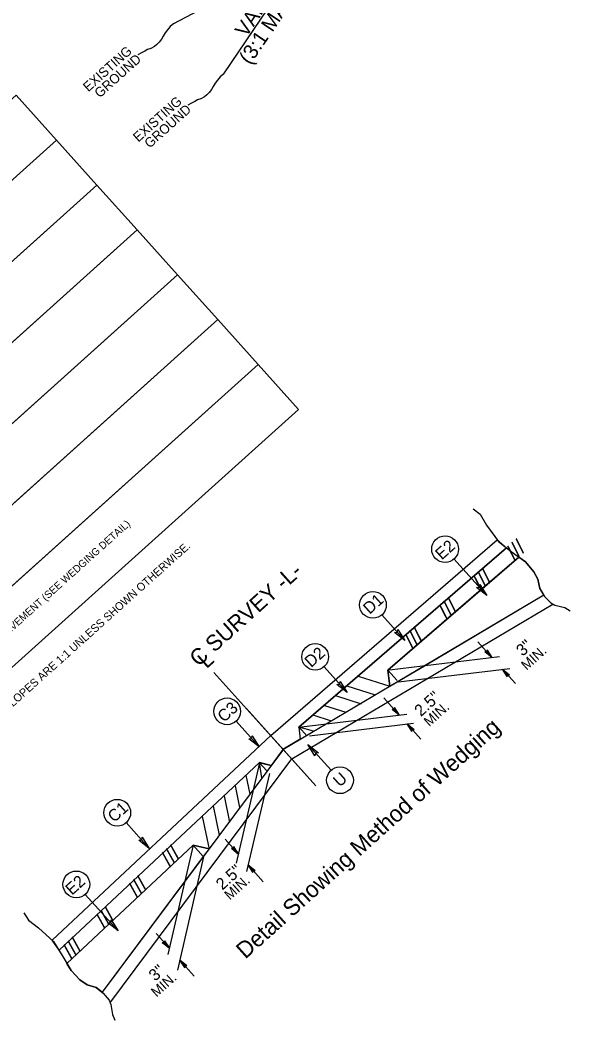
# Model space of a CAD drawing. Extents: x 2488411 to 2488707, y 383669 to 383962.
# Drawn here: x 2488541.5 to 2488578.8, y 383777 to 383844.8 of the extents above; entities that cross this region are included whole.
import ezdxf

# ---------------------------------------------------------------- set-up
doc = ezdxf.new("R2010")
doc.units = 0
for name, color, linetype in [('Old_Level_44', 7, 'Continuous'), ('Prop Dimension', 7, 'Continuous'), ('Prop DSN Text', 7, 'Continuous'), ('Prop Grid Mask', 7, 'Continuous'), ('Prop PFL Pipe Hydraulic Data CELL', 7, 'Continuous'), ('Prop Roadway Profile Bench Mark Info Text', 7, 'Continuous'), ('Sheet Sticker Preliminary CELL', 7, 'Continuous'), ('Sheet Title CELL', 7, 'Continuous'), ('Typical Hinge Slope Arterial CELL', 7, 'Continuous'), ('Typical Text General CELL', 7, 'Continuous'), ('Typical Text ID Circle CELL', 7, 'Continuous')]:
    doc.layers.add(name, color=color, linetype=linetype)

msp = doc.modelspace()

# ---------------------------------------------------------------- linework, layer by layer
at = {"layer": 'Prop DSN Text'}
for p, q in [((2488570.949, 383808.275), (2488573.176, 383805.798)), ((2488566.059, 383804.497), (2488567.625, 383802.755)), ((2488562.138, 383800.973), (2488563.704, 383799.231)), ((2488556.168, 383797.28), (2488557.734, 383795.538)), ((2488562.611, 383793.957), (2488561.045, 383795.699)), ((2488548.719, 383790.408), (2488550.285, 383788.666)), ((2488545.945, 383785.548), (2488548.172, 383783.071))]:
    msp.add_line(p, q, dxfattribs=at)
for centre in [(2488570.343, 383808.949), (2488565.453, 383805.171), (2488561.533, 383801.647), (2488555.563, 383797.954), (2488563.217, 383793.283), (2488548.113, 383791.082), (2488545.339, 383786.222)]:
    msp.add_circle(centre, 0.906, dxfattribs=at)
at = {"layer": 'Prop Grid Mask'}
for points in [[(2488517.29, 383812.671), (2488514.248, 383809.936), (2488511.513, 383812.978), (2488541.261, 383839.72), (2488543.996, 383836.678), (2488517.29, 383812.671), (2488514.555, 383815.713)], [(2488520.025, 383809.629), (2488516.983, 383806.894), (2488514.248, 383809.936), (2488543.996, 383836.678), (2488546.731, 383833.636), (2488520.025, 383809.629), (2488517.29, 383812.671)], [(2488522.76, 383806.586), (2488519.718, 383803.852), (2488516.983, 383806.894), (2488546.731, 383833.636), (2488549.466, 383830.593), (2488522.76, 383806.586), (2488520.025, 383809.629)], [(2488525.495, 383803.544), (2488522.453, 383800.809), (2488519.718, 383803.852), (2488549.465, 383830.593), (2488552.2, 383827.551), (2488525.495, 383803.544), (2488522.76, 383806.586)], [(2488528.23, 383800.502), (2488525.187, 383797.767), (2488522.453, 383800.809), (2488552.2, 383827.551), (2488554.935, 383824.508), (2488528.23, 383800.502), (2488525.495, 383803.544)], [(2488530.965, 383797.46), (2488527.922, 383794.725), (2488525.187, 383797.767), (2488554.935, 383824.508), (2488557.67, 383821.466), (2488530.965, 383797.46), (2488528.23, 383800.502)], [(2488533.699, 383794.417), (2488530.657, 383791.682), (2488527.922, 383794.725), (2488557.67, 383821.466), (2488560.404, 383818.424), (2488533.699, 383794.417), (2488530.965, 383797.46)]]:
    msp.add_lwpolyline(points, dxfattribs=at)
at = {"layer": 'Prop PFL Pipe Hydraulic Data CELL'}
for p, q in [((2488558.525, 383796.306), (2488573.887, 383809.571)), ((2488558.527, 383796.307), (2488573.887, 383809.571)), ((2488573.887, 383809.571), (2488574.519, 383809.042)), ((2488560.428, 383796.875), (2488574.519, 383809.042)), ((2488574.519, 383809.042), (2488560.428, 383796.875)), ((2488566.469, 383800.747), (2488575.349, 383808.414)), ((2488575.349, 383808.414), (2488572.802, 383806.214)), ((2488559.337, 383795.358), (2488577.035, 383805.842)), ((2488572.802, 383806.214), (2488566.469, 383800.747)), ((2488568.945, 383801.049), (2488577.035, 383805.842)), ((2488559.946, 383794.738), (2488577.657, 383805.229)), ((2488572.573, 383802.655), (2488573.515, 383801.607)), ((2488566.584, 383800.761), (2488574.027, 383801.669)), ((2488573.168, 383801.993), (2488573.039, 383801.98)), ((2488573.515, 383801.607), (2488573.039, 383801.98)), ((2488573.515, 383801.607), (2488573.057, 383801.981)), ((2488573.075, 383801.984), (2488573.515, 383801.607)), ((2488573.515, 383801.607), (2488573.093, 383801.986)), ((2488573.112, 383801.987), (2488573.515, 383801.607)), ((2488573.515, 383801.607), (2488573.131, 383801.989)), ((2488573.15, 383801.99), (2488573.515, 383801.607)), ((2488573.195, 383802.12), (2488573.168, 383801.993)), ((2488573.168, 383801.993), (2488573.515, 383801.607)), ((2488573.515, 383801.607), (2488573.172, 383802.011)), ((2488573.176, 383802.029), (2488573.515, 383801.607)), ((2488573.515, 383801.607), (2488573.18, 383802.047)), ((2488573.183, 383802.066), (2488573.515, 383801.607)), ((2488573.515, 383801.607), (2488573.187, 383802.084)), ((2488573.191, 383802.101), (2488573.515, 383801.607)), ((2488573.515, 383801.607), (2488573.195, 383802.12)), ((2488566.593, 383799.656), (2488568.945, 383801.049)), ((2488561.579, 383792.909), (2488554.667, 383800.598)), ((2488564.447, 383800.345), (2488566.593, 383799.656)), ((2488566.594, 383799.657), (2488566.469, 383800.747)), ((2488566.469, 383800.747), (2488567.105, 383800.04)), ((2488566.469, 383800.747), (2488566.593, 383799.656)), ((2488567.188, 383799.948), (2488574.734, 383800.867)), ((2488574.235, 383800.807), (2488575.11, 383799.833)), ((2488574.235, 383800.807), (2488574.712, 383800.433)), ((2488574.235, 383800.807), (2488574.555, 383800.293)), ((2488574.559, 383800.311), (2488574.235, 383800.807)), ((2488574.235, 383800.807), (2488574.563, 383800.329)), ((2488574.566, 383800.347), (2488574.235, 383800.807)), ((2488574.235, 383800.807), (2488574.57, 383800.366)), ((2488574.573, 383800.384), (2488574.235, 383800.807)), ((2488574.235, 383800.807), (2488574.577, 383800.402)), ((2488574.581, 383800.421), (2488574.235, 383800.807)), ((2488574.6, 383800.422), (2488574.235, 383800.807)), ((2488574.235, 383800.807), (2488574.618, 383800.424)), ((2488574.637, 383800.426), (2488574.235, 383800.807)), ((2488574.235, 383800.807), (2488574.655, 383800.428)), ((2488574.674, 383800.429), (2488574.235, 383800.807)), ((2488574.235, 383800.807), (2488574.693, 383800.431)), ((2488574.555, 383800.293), (2488574.581, 383800.421)), ((2488574.581, 383800.421), (2488574.712, 383800.433)), ((2488563.679, 383799.682), (2488565.61, 383799.062)), ((2488562.92, 383799.027), (2488564.652, 383798.472)), ((2488562.171, 383798.35), (2488563.605, 383797.89)), ((2488566.189, 383798.865), (2488567.232, 383797.705)), ((2488561.579, 383792.909), (2488556.859, 383798.161)), ((2488560.615, 383796.898), (2488567.754, 383797.768)), ((2488561.378, 383797.708), (2488562.63, 383797.307)), ((2488566.884, 383798.091), (2488566.754, 383798.079)), ((2488567.232, 383797.705), (2488566.754, 383798.079)), ((2488567.232, 383797.705), (2488566.773, 383798.08)), ((2488566.791, 383798.082), (2488567.232, 383797.705)), ((2488567.232, 383797.705), (2488566.81, 383798.084)), ((2488566.829, 383798.085), (2488567.232, 383797.705)), ((2488567.232, 383797.705), (2488566.847, 383798.088)), ((2488566.865, 383798.089), (2488567.232, 383797.705)), ((2488566.911, 383798.219), (2488566.884, 383798.091)), ((2488566.884, 383798.091), (2488567.232, 383797.705)), ((2488567.232, 383797.705), (2488566.888, 383798.11)), ((2488566.892, 383798.128), (2488567.232, 383797.705)), ((2488567.232, 383797.705), (2488566.896, 383798.146)), ((2488566.899, 383798.164), (2488567.232, 383797.705)), ((2488567.232, 383797.705), (2488566.903, 383798.182)), ((2488566.907, 383798.201), (2488567.232, 383797.705)), ((2488567.232, 383797.705), (2488566.911, 383798.219)), ((2488561.145, 383796.297), (2488568.213, 383797.159)), ((2488567.771, 383797.105), (2488568.704, 383796.068)), ((2488567.771, 383797.105), (2488568.248, 383796.731)), ((2488567.771, 383797.105), (2488568.092, 383796.591)), ((2488568.095, 383796.61), (2488567.771, 383797.105)), ((2488567.771, 383797.105), (2488568.099, 383796.627)), ((2488568.102, 383796.646), (2488567.771, 383797.105)), ((2488567.771, 383797.105), (2488568.106, 383796.664)), ((2488568.11, 383796.682), (2488567.771, 383797.105)), ((2488567.771, 383797.105), (2488568.114, 383796.7)), ((2488568.118, 383796.719), (2488567.771, 383797.105)), ((2488568.137, 383796.721), (2488567.771, 383797.105)), ((2488567.771, 383797.105), (2488568.155, 383796.722)), ((2488568.173, 383796.724), (2488567.771, 383797.105)), ((2488567.771, 383797.105), (2488568.192, 383796.727)), ((2488568.211, 383796.728), (2488567.771, 383797.105)), ((2488567.771, 383797.105), (2488568.229, 383796.73)), ((2488558.525, 383796.306), (2488543.706, 383782.439)), ((2488543.706, 383782.439), (2488558.525, 383796.306)), ((2488560.415, 383796.844), (2488560.438, 383796.862)), ((2488560.428, 383796.875), (2488560.524, 383796.063)), ((2488560.428, 383796.875), (2488560.524, 383796.063)), ((2488561.426, 383796.606), (2488560.441, 383796.878)), ((2488560.441, 383796.878), (2488560.962, 383796.298)), ((2488568.092, 383796.591), (2488568.118, 383796.719)), ((2488568.118, 383796.719), (2488568.248, 383796.731)), ((2488560.524, 383796.063), (2488559.337, 383795.358)), ((2488559.382, 383795.398), (2488547.079, 383778.914)), ((2488559.337, 383795.358), (2488558.554, 383794.292)), ((2488557.769, 383794.485), (2488544.165, 383781.755)), ((2488557.769, 383794.485), (2488544.165, 383781.755)), ((2488559.934, 383794.727), (2488547.65, 383778.268)), ((2488557.761, 383794.458), (2488556.187, 383787.658)), ((2488557.92, 383793.454), (2488557.754, 383794.462)), ((2488557.754, 383794.462), (2488558.227, 383793.936)), ((2488558.554, 383794.292), (2488557.769, 383794.485)), ((2488557.783, 383794.469), (2488558.554, 383794.292)), ((2488556.829, 383793.618), (2488557.095, 383792.332)), ((2488558.426, 383793.739), (2488556.884, 383787.086)), ((2488556.106, 383792.898), (2488556.411, 383791.424)), ((2488555.354, 383792.225), (2488555.722, 383790.444)), ((2488554.621, 383791.54), (2488555.034, 383789.555)), ((2488553.882, 383790.848), (2488554.346, 383788.607)), ((2488553.266, 383788.878), (2488544.701, 383780.863)), ((2488544.701, 383780.863), (2488553.266, 383788.878)), ((2488553.266, 383788.878), (2488551.55, 383781.472)), ((2488554.34, 383788.638), (2488553.266, 383788.878)), ((2488553.266, 383788.878), (2488553.95, 383788.117)), ((2488553.266, 383788.878), (2488554.337, 383788.639)), ((2488555.42, 383789.289), (2488556.33, 383788.278)), ((2488556.01, 383788.792), (2488555.983, 383788.664)), ((2488556.33, 383788.278), (2488556.001, 383788.755)), ((2488556.006, 383788.774), (2488556.33, 383788.278)), ((2488556.33, 383788.278), (2488556.01, 383788.792)), ((2488553.968, 383788.09), (2488552.209, 383780.417)), ((2488553.949, 383788.118), (2488552.704, 383786.449)), ((2488554.337, 383788.639), (2488553.949, 383788.118)), ((2488555.983, 383788.664), (2488555.853, 383788.651)), ((2488556.33, 383788.278), (2488555.853, 383788.651)), ((2488556.33, 383788.278), (2488555.871, 383788.653)), ((2488555.89, 383788.654), (2488556.33, 383788.278)), ((2488556.33, 383788.278), (2488555.908, 383788.657)), ((2488555.927, 383788.659), (2488556.33, 383788.278)), ((2488556.33, 383788.278), (2488555.946, 383788.66)), ((2488555.964, 383788.662), (2488556.33, 383788.278)), ((2488555.983, 383788.664), (2488556.33, 383788.278)), ((2488556.33, 383788.278), (2488555.987, 383788.682)), ((2488555.99, 383788.7), (2488556.33, 383788.278)), ((2488556.33, 383788.278), (2488555.994, 383788.719)), ((2488555.997, 383788.737), (2488556.33, 383788.278)), ((2488556.99, 383787.544), (2488558.014, 383786.405)), ((2488556.99, 383787.544), (2488557.468, 383787.171)), ((2488556.99, 383787.544), (2488557.311, 383787.029)), ((2488557.314, 383787.048), (2488556.99, 383787.544)), ((2488556.99, 383787.544), (2488557.318, 383787.066)), ((2488557.321, 383787.085), (2488556.99, 383787.544)), ((2488556.99, 383787.544), (2488557.326, 383787.103)), ((2488557.33, 383787.121), (2488556.99, 383787.544)), ((2488556.99, 383787.544), (2488557.333, 383787.139)), ((2488557.337, 383787.157), (2488556.99, 383787.544)), ((2488557.355, 383787.159), (2488556.99, 383787.544)), ((2488556.99, 383787.544), (2488557.374, 383787.161)), ((2488557.392, 383787.163), (2488556.99, 383787.544)), ((2488556.99, 383787.544), (2488557.41, 383787.165)), ((2488557.429, 383787.166), (2488556.99, 383787.544)), ((2488556.99, 383787.544), (2488557.449, 383787.169)), ((2488557.311, 383787.029), (2488557.337, 383787.157)), ((2488557.337, 383787.157), (2488557.468, 383787.171)), ((2488552.704, 383786.449), (2488547.079, 383778.914)), ((2488550.741, 383782.897), (2488551.647, 383781.888)), ((2488544.165, 383781.755), (2488543.706, 383782.439)), ((2488551.3, 383782.275), (2488551.17, 383782.261)), ((2488551.647, 383781.888), (2488551.17, 383782.261)), ((2488551.647, 383781.888), (2488551.188, 383782.264)), ((2488551.208, 383782.266), (2488551.647, 383781.888)), ((2488551.647, 383781.888), (2488551.226, 383782.268)), ((2488551.244, 383782.27), (2488551.647, 383781.888)), ((2488551.647, 383781.888), (2488551.263, 383782.272)), ((2488551.281, 383782.273), (2488551.647, 383781.888)), ((2488551.327, 383782.403), (2488551.3, 383782.275)), ((2488551.3, 383782.275), (2488551.647, 383781.888)), ((2488551.647, 383781.888), (2488551.303, 383782.293)), ((2488551.308, 383782.312), (2488551.647, 383781.888)), ((2488551.647, 383781.888), (2488551.311, 383782.33)), ((2488551.315, 383782.348), (2488551.647, 383781.888)), ((2488551.647, 383781.888), (2488551.319, 383782.366)), ((2488551.323, 383782.385), (2488551.647, 383781.888)), ((2488551.647, 383781.888), (2488551.327, 383782.403)), ((2488552.365, 383781.091), (2488553.334, 383780.012)), ((2488552.365, 383781.091), (2488552.842, 383780.717)), ((2488552.365, 383781.091), (2488552.685, 383780.576)), ((2488552.69, 383780.595), (2488552.365, 383781.091)), ((2488552.365, 383781.091), (2488552.693, 383780.614)), ((2488552.697, 383780.632), (2488552.365, 383781.091)), ((2488552.365, 383781.091), (2488552.7, 383780.65)), ((2488552.704, 383780.668), (2488552.365, 383781.091)), ((2488552.365, 383781.091), (2488552.709, 383780.686)), ((2488552.712, 383780.705), (2488552.365, 383781.091)), ((2488552.731, 383780.706), (2488552.365, 383781.091)), ((2488552.365, 383781.091), (2488552.749, 383780.708)), ((2488552.767, 383780.711), (2488552.365, 383781.091)), ((2488552.365, 383781.091), (2488552.786, 383780.712)), ((2488552.805, 383780.714), (2488552.365, 383781.091)), ((2488552.365, 383781.091), (2488552.823, 383780.716)), ((2488552.685, 383780.576), (2488552.712, 383780.705)), ((2488552.712, 383780.705), (2488552.842, 383780.717))]:
    msp.add_line(p, q, dxfattribs=at)
for points in [[(2488572.237, 383811.688), (2488572.715, 383811.318), (2488573.159, 383810.581), (2488573.967, 383809.468), (2488574.836, 383808.796), (2488575.792, 383808.083), (2488576.369, 383807.415), (2488576.634, 383806.904), (2488576.767, 383806.272), (2488577.096, 383805.745), (2488577.517, 383805.302), (2488577.791, 383805.159), (2488578.457, 383804.983), (2488578.815, 383804.773)], [(2488577.035, 383805.842), (2488576.767, 383806.272), (2488576.634, 383806.904), (2488576.369, 383807.415), (2488575.792, 383808.083), (2488575.349, 383808.414)], [(2488541.775, 383784.304), (2488542.092, 383783.79), (2488542.778, 383783.27), (2488543.799, 383782.348), (2488544.374, 383781.413), (2488544.983, 383780.387), (2488545.586, 383779.743), (2488546.066, 383779.424), (2488546.68, 383779.226), (2488547.169, 383778.843), (2488547.565, 383778.376), (2488547.677, 383778.089), (2488547.782, 383777.408), (2488547.953, 383777.029)], [(2488547.079, 383778.913), (2488546.68, 383779.226), (2488546.066, 383779.424), (2488545.586, 383779.743), (2488544.983, 383780.387), (2488544.701, 383780.863)]]:
    msp.add_lwpolyline(points, dxfattribs=at)
at = {"layer": 'Sheet Sticker Preliminary CELL'}
for points in [[(2488572.701, 383806.553), (2488573.176, 383805.798), (2488572.469, 383806.351), (2488572.66, 383806.372)], [(2488567.15, 383803.51), (2488567.625, 383802.755), (2488566.918, 383803.308), (2488567.109, 383803.329)], [(2488567.15, 383803.51), (2488567.625, 383802.755), (2488566.918, 383803.308), (2488567.109, 383803.329)], [(2488563.229, 383799.986), (2488563.704, 383799.231), (2488562.997, 383799.784), (2488563.189, 383799.805)], [(2488563.229, 383799.986), (2488563.704, 383799.231), (2488562.997, 383799.784), (2488563.189, 383799.805)], [(2488557.259, 383796.293), (2488557.734, 383795.538), (2488557.027, 383796.091), (2488557.219, 383796.112)], [(2488557.259, 383796.293), (2488557.734, 383795.538), (2488557.027, 383796.091), (2488557.219, 383796.112)], [(2488561.52, 383794.944), (2488561.045, 383795.699), (2488561.752, 383795.146), (2488561.561, 383795.125)], [(2488561.52, 383794.944), (2488561.045, 383795.699), (2488561.752, 383795.146), (2488561.561, 383795.125)], [(2488549.81, 383789.421), (2488550.285, 383788.666), (2488549.578, 383789.219), (2488549.769, 383789.24)], [(2488549.81, 383789.421), (2488550.285, 383788.666), (2488549.578, 383789.219), (2488549.769, 383789.24)], [(2488547.697, 383783.826), (2488548.172, 383783.071), (2488547.465, 383783.624), (2488547.656, 383783.645)], [(2488547.697, 383783.826), (2488548.172, 383783.071), (2488547.465, 383783.624), (2488547.656, 383783.645)]]:
    msp.add_lwpolyline(points, close=True, dxfattribs=at)
at = {"layer": 'Typical Text General CELL'}
for p in [(2488551.942, 383844.576), (2488555.33, 383841.167)]:
    msp.add_line(p, (2488560.797, 383849.268), dxfattribs=at)
at = {"layer": 'Typical Text ID Circle CELL'}
for points in [[(2488551.942, 383844.576), (2488551.71, 383844.374), (2488551.525, 383844.162), (2488551.354, 383843.96), (2488551.217, 383843.72), (2488551.108, 383843.528), (2488550.961, 383843.325), (2488550.804, 383843.161), (2488550.648, 383843.02), (2488550.394, 383842.885), (2488550.168, 383842.823), (2488549.988, 383842.709), (2488549.76, 383842.598), (2488549.505, 383842.463)], [(2488555.33, 383841.167), (2488555.099, 383840.965), (2488554.914, 383840.752), (2488554.743, 383840.551), (2488554.606, 383840.311), (2488554.497, 383840.119), (2488554.35, 383839.916), (2488554.193, 383839.751), (2488554.037, 383839.611), (2488553.782, 383839.476), (2488553.556, 383839.414), (2488553.377, 383839.3), (2488553.148, 383839.188), (2488552.894, 383839.053)]]:
    msp.add_lwpolyline(points, dxfattribs=at)

# ---------------------------------------------------------------- texts
at = {"layer": 'Old_Level_44'}
for s, p in [('E2', (2488570.122, 383808.18)), ('D1', (2488565.226, 383804.494)), ('D2', (2488561.26, 383800.883)), ('C3', (2488555.351, 383797.166)), ('U', (2488563.2, 383792.78)), ('C1', (2488547.908, 383790.38)), ('E2', (2488545.04, 383785.449))]:
    msp.add_text(s, height=0.8, rotation=41.95382, dxfattribs=at).set_placement(p)
at = {"layer": 'Prop Dimension'}
msp.add_text('Detail Showing Method of Wedging', height=1.11896, rotation=41.95382, dxfattribs=at).set_placement((2488556.798, 383781.121))
at = {"layer": 'Prop Grid Mask'}
for s, height, p in [('VARIABLE DEPTH ASPHALT PAVEMENT (SEE WEDGING DETAIL)', 0.5, (2488533.595, 383796.715)), ('NOTE: PAVEMENT EDGE SLOPES ARE 1:1 UNLESS SHOWN OTHERWISE.', 0.54417, (2488534.06, 383791.963))]:
    msp.add_text(s, height=height, rotation=41.95382, dxfattribs=at).set_placement(p)
at = {"layer": 'Prop PFL Pipe Hydraulic Data CELL'}
for s, height, rotation, p in [('/// ', 1.0176, 40.80753, (2488575.039, 383808.154)), ('/// ', 1.0176, 40.80919, (2488572.753, 383806.147)), ('/// ', 1.0172, 40.80743, (2488570.427, 383804.177)), ('/// ', 1.0172, 40.80909, (2488568.116, 383802.184)), ('3"', 0.8, 41.95382, (2488575.601, 383801.645)), ('MIN.', 0.6779, 41.95382, (2488575.871, 383800.704)), ('2.5"', 0.8, 41.95382, (2488568.702, 383797.553)), ('MIN.', 0.6779, 41.95382, (2488569.271, 383796.885)), ('/// ', 1.0172, 43.10012, (2488551.664, 383787.394)), ('2.5"', 0.8, 41.95382, (2488555.244, 383785.793)), ('/// ', 1.0172, 43.09836, (2488549.437, 383785.308)), ('MIN.', 0.6779, 41.95382, (2488555.75, 383785.126)), ('/// ', 1.0176, 43.10022, (2488547.23, 383783.203)), ('/// ', 1.0176, 43.09855, (2488544.992, 383781.143)), ('3"', 0.8, 41.95382, (2488550.685, 383779.615)), ('MIN.', 0.6779, 41.95382, (2488550.778, 383778.543))]:
    msp.add_text(s, height=height, rotation=rotation, dxfattribs=at).set_placement(p)
at = {"layer": 'Prop Roadway Profile Bench Mark Info Text'}
for s, p in [('(3:1 MAX)', (2488557.129, 383841.727)), ('VAR.', (2488556.857, 383843.591))]:
    msp.add_text(s, height=1, rotation=55.99007, dxfattribs=at).set_placement(p)
at = {"layer": 'Sheet Title CELL'}
for s, p in [('EXISTING', (2488546.153, 383839.919)), ('GROUND', (2488546.925, 383839.504)), ('EXISTING', (2488549.542, 383836.509)), ('GROUND', (2488550.314, 383836.095))]:
    msp.add_text(s, height=0.65, rotation=41.95382, dxfattribs=at).set_placement(p)
at = {"layer": 'Typical Hinge Slope Arterial CELL'}
for s, height, p in [('C SURVEY -L-', 1.0817, (2488553.616, 383800.934)), ('L', 1.082, (2488554.163, 383800.804))]:
    msp.add_text(s, height=height, rotation=41.95382, dxfattribs=at).set_placement(p)

doc.saveas('drawing.dxf')
